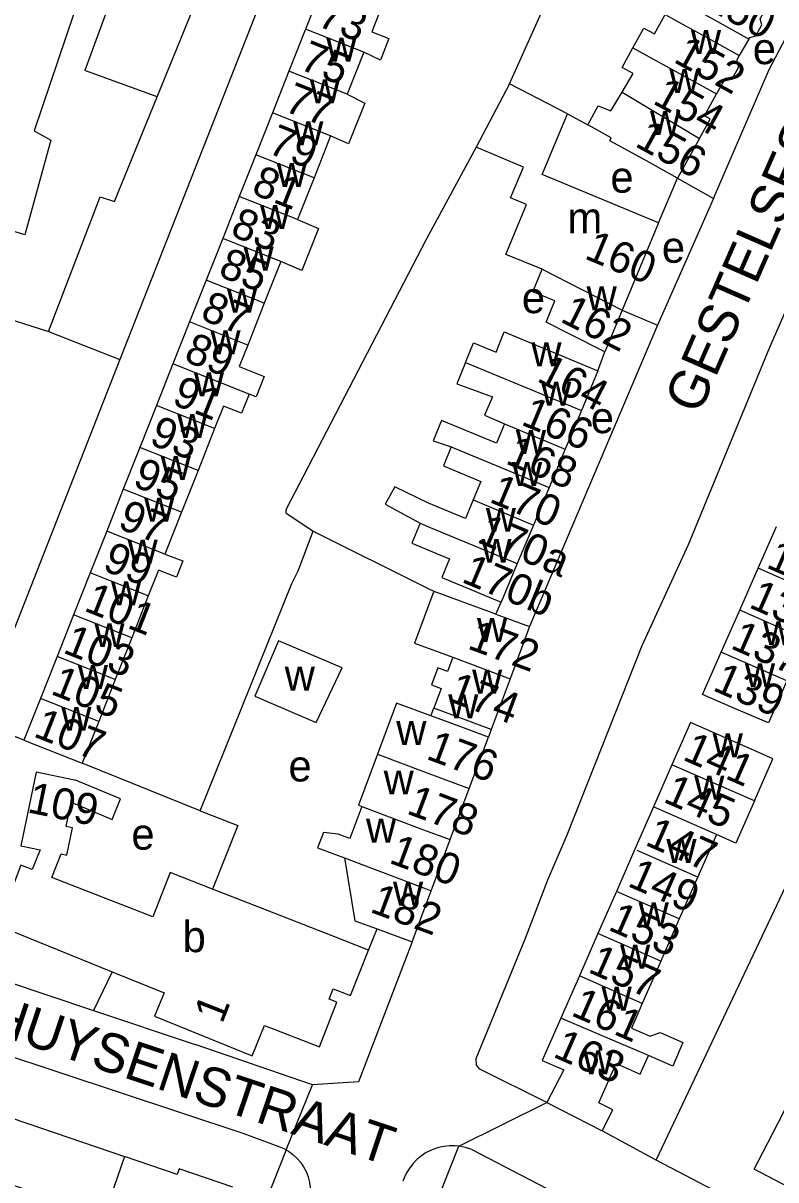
# Model space of a CAD drawing. Extents: x 159700 to 161346, y 381730 to 382922.
# Drawn here: x 160648.4 to 160744.8, y 381991.4 to 382139.7 of the extents above; entities that cross this region are included whole.
import ezdxf

# ---------------------------------------------------------------- set-up
doc = ezdxf.new("R2010")
doc.units = 0
for name, color, linetype in [('BLT_Basislijn', 7, 'Continuous'), ('BLT_Bebouwing', 7, 'Continuous'), ('BLT_Centroide', 7, 'Continuous'), ('BLT_Huisnummer', 7, 'Continuous'), ('BLT_Huisnummer_ tussenligend', 7, 'Continuous'), ('BLT_Huisnummer_reeks', 7, 'Continuous'), ('BLT_Onderdoorgang_en_onderverdeling', 7, 'Continuous'), ('BLT_Onderverdeling_panden', 7, 'Continuous'), ('BLT_Straatnaam', 7, 'Continuous'), ('BLT_Vlakafsluiter', 7, 'Continuous')]:
    doc.layers.add(name, color=color, linetype=linetype)

msp = doc.modelspace()

# ---------------------------------------------------------------- linework, layer by layer
at = {"layer": 'BLT_Basislijn'}
for p, q in [((160660.9, 382146.35), (160656.26, 382133.57)), ((160665.52, 382130.2), (160670.65, 382142.8)), ((160710.65, 382131.9), (160715.16, 382141.87)), ((160665.52, 382130.2), (160656.26, 382133.57)), ((160718.09, 382128.02), (160720.67, 382126.62)), ((160729.76, 382114.05), (160732.18, 382119.8)), ((160732.18, 382119.8), (160736.77, 382117.18)), ((160736.77, 382117.18), (160729.6, 382100.96)), ((160642.5, 382103.07), (160651.59, 382100.14)), ((160725.09, 382102.86), (160729.6, 382100.96)), ((160729.6, 382100.96), (160713.22, 382062.32)), ((160651.59, 382100.14), (160660.75, 382096.55)), ((160660.75, 382096.55), (160642.54, 382050.16)), ((160721.96, 382095.09), (160722.86, 382097.54)), ((160685.49, 382074.56), (160700, 382067.35)), ((160708.91, 382063.93), (160709.59, 382065.44)), ((160648.45, 382047.77), (160642.54, 382050.16)), ((160671.01, 382038.73), (160655.91, 382044.82)), ((160692.58, 382020.87), (160693.71, 382023.58)), ((160659.74, 382018.09), (160657.35, 382013.14)), ((160657.35, 382013.14), (160670.38, 382008.78)), ((160636.62, 382010.62), (160676.49, 381997.4)), ((160632.68, 382004.19), (160661.34, 381994.43)), ((160676.49, 381997.4), (160681.1, 381995.72)), ((160700, 381985.25), (160704.17, 381995.74)), ((160682.03, 381995.28), (160679.52, 381988.9)), ((160705.83, 381995.32), (160854.54, 381918.26))]:
    msp.add_line(p, q, dxfattribs=at)
for points in [[(160681.91, 382220.18), (160679.43, 382214.59), (160683.36, 382212.77), (160677.31, 382195.82), (160674.59, 382196.42), (160665.51, 382171.9), (160668.53, 382170.99), (160661.57, 382151.91), (160658.85, 382152.82), (160649.77, 382125.87), (160651.89, 382124.66), (160648.56, 382112.55), (160645.53, 382113.46), (160642.5, 382103.07)], [(160736.77, 382117.18), (160743.9, 382133.7), (160755.59, 382155.95), (160755.73, 382156.22)], [(160683.48, 382154.46), (160683.02, 382153.28), (160660.75, 382096.55)], [(160715.43, 382001.34), (160706.86, 382005.62), (160706.44, 382006.13), (160706.37, 382006.99), (160712.72, 382022.39), (160715.55, 382029.86), (160718.04, 382035.66), (160727.65, 382059.9), (160733.57, 382072.85), (160744.01, 382098.14), (160747.46, 382106.03), (160752.09, 382115.65), (160758.89, 382130.51), (160762.59, 382138.01), (160762.83, 382138.43)], [(160651.59, 382100.14), (160658.24, 382117.4), (160660.06, 382116.79), (160665.52, 382130.2)], [(160706.39, 382123.75), (160700, 382111.92)], [(160729.44, 381993.93), (160779.67, 382100.1), (160781.16, 382102.9), (160789.01, 382119.93)], [(160700, 382111.92), (160682, 382077.28), (160682, 382076.92), (160685.49, 382074.56)], [(160815.18, 382106.64), (160803.51, 382084.65), (160803.12, 382084.2), (160792.72, 382064.24), (160788.1, 382054.81), (160779.42, 382038.85), (160769.7, 382019.74), (160767.41, 382015.7), (160755.12, 381991.74), (160751.34, 381984.02), (160750.55, 381983.57), (160749.53, 381983.44), (160729.44, 381993.93)], [(160671.01, 382038.73), (160682.77, 382067.84), (160683.6, 382069.48), (160685.49, 382074.56)], [(160700, 382067.35), (160700.34, 382067.18), (160700.97, 382066.88)], [(160642.54, 382050.16), (160642.45, 382049.95), (160632.17, 382023.66), (160633.53, 382021.46), (160634.31, 382020.85), (160657.35, 382013.14)], [(160671.01, 382038.73), (160675.84, 382036.83), (160672.62, 382028.67)], [(160698.19, 382021.91), (160691.33, 382003.98), (160685.44, 382003.61)], [(160685.44, 382003.61), (160670.38, 382008.78)], [(160729.44, 381993.93), (160722.53, 381997.71)], [(160681.1, 381995.72), (160681.74, 381995.45), (160682.03, 381995.28)], [(160704.17, 381995.74), (160703.71, 381995.8), (160702.98, 381995.8), (160702.25, 381995.72), (160701.54, 381995.56), (160700.85, 381995.33), (160700.19, 381995.02), (160700, 381994.92)], [(160705.83, 381995.32), (160705.14, 381995.55), (160704.43, 381995.71), (160704.17, 381995.74)], [(160682.03, 381995.28), (160682.35, 381995.1), (160682.92, 381994.69), (160683.43, 381994.21), (160683.89, 381993.68), (160684.28, 381993.1), (160684.6, 381992.48), (160684.86, 381991.83), (160685.03, 381991.15), (160685.13, 381990.45), (160685.15, 381989.75), (160685.08, 381989.06), (160684.94, 381988.37), (160684.72, 381987.71), (160684.46, 381987.12)], [(160700, 381994.92), (160699.39, 381994.52), (160698.83, 381994.06), (160698.32, 381993.53), (160697.87, 381992.96), (160697.48, 381992.34), (160697.17, 381991.68), (160697.01, 381991.27)]]:
    msp.add_lwpolyline(points, dxfattribs=at)
at = {"layer": 'BLT_Bebouwing'}
for p, q in [((160686.65, 382144.24), (160684.53, 382138.88)), ((160684.53, 382138.88), (160682.4, 382133.52)), ((160741.32, 382137.61), (160740.08, 382135.53)), ((160691.98, 382135.93), (160689.86, 382130.57)), ((160682.4, 382133.52), (160680.28, 382128.16)), ((160710.65, 382131.9), (160706.39, 382123.75)), ((160718.09, 382128.02), (160710.65, 382131.9)), ((160680.28, 382128.16), (160678.16, 382122.8)), ((160714.86, 382120.27), (160718.09, 382128.02)), ((160687.74, 382125.21), (160685.62, 382119.85)), ((160734.98, 382124.88), (160732.18, 382119.8)), ((160678.16, 382122.8), (160676.04, 382117.44)), ((160729.76, 382114.05), (160714.86, 382120.27)), ((160685.62, 382119.85), (160683.49, 382114.49)), ((160676.04, 382117.44), (160673.92, 382112.08)), ((160729.76, 382114.05), (160725.09, 382102.86)), ((160673.92, 382112.08), (160671.8, 382106.72)), ((160681.37, 382109.13), (160679.25, 382103.77)), ((160671.8, 382106.72), (160669.67, 382101.36)), ((160679.25, 382103.77), (160677.13, 382098.41)), ((160725.09, 382102.86), (160722.86, 382097.54)), ((160669.67, 382101.36), (160667.55, 382096.01)), ((160667.55, 382096.01), (160665.43, 382090.65)), ((160721.96, 382095.09), (160719.86, 382090.03)), ((160665.43, 382090.65), (160663.31, 382085.29)), ((160719.86, 382090.03), (160717.79, 382085.08)), ((160672.88, 382087.7), (160670.76, 382082.34)), ((160663.31, 382085.29), (160661.18, 382079.93)), ((160717.79, 382085.08), (160715.73, 382080.14)), ((160670.76, 382082.34), (160668.64, 382076.98)), ((160715.73, 382080.14), (160713.72, 382075.33)), ((160661.18, 382079.93), (160659.06, 382074.57)), ((160668.64, 382076.98), (160666.52, 382071.62)), ((160659.06, 382074.57), (160656.94, 382069.21)), ((160713.72, 382075.33), (160711.65, 382070.39)), ((160742.51, 382069.8), (160744.86, 382075.17)), ((160711.65, 382070.39), (160709.59, 382065.44)), ((160740.15, 382064.42), (160742.51, 382069.8)), ((160656.94, 382069.21), (160654.82, 382063.85)), ((160664.39, 382066.26), (160662.27, 382060.9)), ((160654.82, 382063.85), (160652.7, 382058.49)), ((160708.91, 382063.93), (160713.22, 382062.32)), ((160737.79, 382059.05), (160740.15, 382064.42)), ((160713.22, 382062.32), (160710.74, 382055.65)), ((160662.27, 382060.9), (160660.15, 382055.54)), ((160652.7, 382058.49), (160650.58, 382053.13)), ((160660.15, 382055.54), (160658.03, 382050.18)), ((160710.74, 382055.65), (160708.32, 382049.14)), ((160650.58, 382053.13), (160648.45, 382047.77)), ((160700.6, 382050.89), (160700.96, 382051.87)), ((160658.03, 382050.18), (160655.91, 382044.82)), ((160708.32, 382049.14), (160707.95, 382048.15)), ((160705.51, 382041.59), (160707.95, 382048.15)), ((160731.47, 382044.62), (160729.1, 382039.21)), ((160703.07, 382035.03), (160705.51, 382041.59)), ((160729.1, 382039.21), (160726.72, 382033.8)), ((160737.16, 382035.68), (160734.78, 382030.27)), ((160700.63, 382028.47), (160703.07, 382035.03)), ((160689.52, 382032.68), (160690.84, 382024.64)), ((160726.72, 382033.8), (160724.35, 382028.39)), ((160734.78, 382030.27), (160732.41, 382024.86)), ((160678.77, 382026.27), (160672.62, 382028.67)), ((160700, 382026.77), (160700.63, 382028.47)), ((160724.35, 382028.39), (160721.98, 382022.98)), ((160698.19, 382021.91), (160700, 382026.77)), ((160645.11, 382024.03), (160659.74, 382018.09)), ((160690.84, 382024.64), (160693.71, 382023.58)), ((160732.41, 382024.86), (160730.04, 382019.44)), ((160693.71, 382023.58), (160698.19, 382021.91)), ((160721.98, 382022.98), (160719.61, 382017.57)), ((160730.04, 382019.44), (160727.66, 382014.03)), ((160719.61, 382017.57), (160717.23, 382012.16))]:
    msp.add_line(p, q, dxfattribs=at)
for points in [[(160741.32, 382137.61), (160741.44, 382137.82), (160742.2, 382138.04), (160742.98, 382139.46), (160742.75, 382140.23), (160744.13, 382142.74)], [(160694.1, 382141.28), (160693.02, 382138.55), (160695.21, 382137.68), (160694.12, 382134.93), (160691.98, 382135.93)], [(160726.47, 382136.51), (160727.86, 382139.03), (160729.21, 382138.28), (160730.58, 382140.77), (160732.45, 382139.74)], [(160725.08, 382130.81), (160726.51, 382133.2), (160725.08, 382133.99), (160726.47, 382136.51)], [(160740.08, 382135.53), (160739.73, 382134.89), (160739.99, 382134.01), (160739.2, 382132.58), (160738.28, 382132.56), (160737.19, 382130.59)], [(160689.86, 382130.57), (160692.11, 382129.42), (160690.04, 382124.18), (160687.74, 382125.21)], [(160720.67, 382126.62), (160722.01, 382129.05), (160723.65, 382128.42), (160725.08, 382130.81)], [(160734.98, 382124.88), (160736.34, 382127.36), (160735.63, 382127.76), (160737.19, 382130.59)], [(160732.18, 382119.8), (160727.8, 382122.21), (160723.51, 382124.58), (160723.7, 382124.95), (160720.67, 382126.62)], [(160714.86, 382108.12), (160710.18, 382110.02), (160712.85, 382116.42), (160710.8, 382117.28), (160712.44, 382121.22), (160706.39, 382123.75)], [(160683.49, 382114.49), (160686.19, 382113.34), (160684.06, 382107.96), (160681.37, 382109.13)], [(160722.86, 382097.54), (160718.4, 382099.79), (160715.37, 382101.33), (160716.48, 382104.05), (160713.65, 382105.23), (160714.86, 382108.12)], [(160705.02, 382096.18), (160706.05, 382098.68), (160708.93, 382097.5), (160709.99, 382100.08), (160721.96, 382095.09)], [(160677.13, 382098.41), (160676.03, 382095.65), (160679.25, 382094.37), (160678.22, 382091.76), (160677.31, 382092.12)], [(160705.02, 382096.18), (160703.9, 382093.45), (160704.96, 382093.06), (160708.46, 382091.78), (160707.46, 382089.4), (160710.02, 382088.32)], [(160677.31, 382092.12), (160676.34, 382089.67), (160674.03, 382090.59), (160672.88, 382087.7)], [(160710.02, 382088.32), (160708.97, 382085.81), (160701.96, 382088.74), (160700.88, 382086.15), (160703.2, 382085.37)], [(160703.2, 382085.37), (160702.19, 382082.94), (160707, 382080.93), (160706.01, 382078.55)], [(160695.95, 382080.24), (160694.74, 382078.03), (160699.2, 382075.59)], [(160706.01, 382078.55), (160705.01, 382076.17), (160700.27, 382078.15), (160695.95, 382080.24)], [(160699.2, 382075.59), (160698.13, 382073.03), (160700, 382072.25)], [(160666.52, 382071.62), (160668.81, 382070.76), (160667.98, 382068.67), (160665.71, 382069.57), (160664.39, 382066.26)], [(160700, 382072.25), (160702.96, 382071.01), (160701.97, 382068.63), (160704.98, 382067.37), (160709.59, 382065.44)], [(160700.97, 382066.88), (160698.48, 382060.21), (160703.39, 382058.39)], [(160700.97, 382066.88), (160708.54, 382064.07), (160708.91, 382063.93)], [(160703.39, 382058.39), (160702.72, 382056.57), (160701.48, 382057.03), (160700.67, 382054.85), (160701.9, 382054.39), (160700.96, 382051.87)], [(160746.19, 382055.37), (160743.83, 382049.99), (160739.98, 382051.6), (160735.4, 382053.61), (160737.79, 382059.05)], [(160700.6, 382050.89), (160696.2, 382052.52), (160693.76, 382045.96)], [(160742.03, 382039.99), (160744.4, 382045.4), (160741.9, 382046.49), (160738.42, 382048.02), (160733.84, 382050.03), (160731.47, 382044.62)], [(160648.45, 382047.77), (160653.1, 382045.93), (160655.91, 382044.82)], [(160693.76, 382045.96), (160691.33, 382039.44), (160691.73, 382039.29)], [(160672.62, 382028.67), (160667.2, 382030.8), (160664.98, 382025.12), (160652.03, 382030.19), (160653.21, 382033.2), (160653.95, 382033.05), (160654.67, 382036.53), (160653.85, 382036.7), (160654.49, 382039.81), (160659.76, 382037.62), (160660.84, 382040.24), (160655.08, 382042.63), (160654.92, 382042.66), (160650.02, 382043.67), (160648.07, 382034.22), (160650.52, 382033.71), (160649.53, 382031.19), (160648.07, 382031.76), (160645.11, 382024.03)], [(160742.03, 382039.99), (160739.67, 382034.59), (160737.16, 382035.68)], [(160691.73, 382039.29), (160690.19, 382035.17), (160688.69, 382035.73), (160686.81, 382035.93), (160686.08, 382033.96), (160689.52, 382032.68)], [(160692.58, 382020.87), (160687.92, 382022.69), (160678.77, 382026.27)], [(160659.74, 382018.09), (160666.41, 382015.39), (160665.2, 382012.39), (160677.7, 382007.32), (160679.28, 382011.2), (160686.32, 382008.47), (160688.55, 382014.21), (160687.55, 382014.6), (160688.06, 382015.9), (160690.29, 382015.03), (160692.58, 382020.87)], [(160727.66, 382014.03), (160726.28, 382010.88), (160728.66, 382009.84), (160729.94, 382010.32), (160732.88, 382009.04), (160731.56, 382006.01), (160728.45, 382007.36)], [(160717.23, 382012.16), (160714.86, 382006.74), (160717.6, 382005.54), (160715.43, 382001.34)], [(160722.53, 381997.71), (160723.9, 382000.39), (160722.09, 382001.31), (160724.3, 382006.35), (160727.41, 382004.99), (160728.45, 382007.36)], [(160715.43, 382001.34), (160722.53, 381997.71)], [(160753.56, 381996.34), (160749.64, 381988.8), (160741.98, 381992.78), (160744.29, 381997.22), (160745.9, 382000.32)], [(160661.34, 381994.43), (160658.67, 381986.71), (160646.51, 381990.91), (160646.97, 381992.25), (160641.84, 381994.02), (160641.37, 381992.68), (160630.13, 381996.56)], [(160675.22, 381990.48), (160668.35, 381992.85), (160668.09, 381992.1), (160661.34, 381994.43)]]:
    msp.add_lwpolyline(points, dxfattribs=at)
msp.add_lwpolyline([(160681.08, 382060.51), (160678.05, 382053.41), (160685.91, 382050.05), (160689.21, 382057.04)], close=True, dxfattribs=at)
at = {"layer": 'BLT_Onderdoorgang_en_onderverdeling'}
for points in [[(160741.32, 382137.61), (160736.94, 382140.03), (160733.62, 382141.86)], [(160732.45, 382139.74), (160735.7, 382137.94), (160740.08, 382135.53)], [(160708.32, 382049.14), (160703.63, 382050.88), (160700.96, 382051.87)], [(160707.95, 382048.15), (160703.27, 382049.9), (160700.6, 382050.89)]]:
    msp.add_lwpolyline(points, dxfattribs=at)
at = {"layer": 'BLT_Onderverdeling_panden'}
for p, q in [((160691.98, 382135.93), (160684.53, 382138.88)), ((160726.47, 382136.51), (160737.19, 382130.59)), ((160689.86, 382130.57), (160682.4, 382133.52)), ((160725.08, 382130.81), (160734.98, 382124.88)), ((160687.74, 382125.21), (160680.28, 382128.16)), ((160685.62, 382119.85), (160678.16, 382122.8)), ((160683.49, 382114.49), (160676.04, 382117.44)), ((160681.37, 382109.13), (160673.92, 382112.08)), ((160679.25, 382103.77), (160671.8, 382106.72)), ((160714.86, 382108.12), (160725.09, 382102.86)), ((160677.13, 382098.41), (160669.67, 382101.36)), ((160677.31, 382092.12), (160667.55, 382096.01)), ((160705.02, 382096.18), (160719.86, 382090.03)), ((160672.88, 382087.7), (160665.43, 382090.65)), ((160710.02, 382088.32), (160717.79, 382085.08)), ((160670.76, 382082.34), (160663.31, 382085.29)), ((160703.2, 382085.37), (160715.73, 382080.14)), ((160668.64, 382076.98), (160661.18, 382079.93)), ((160706.01, 382078.55), (160713.72, 382075.33)), ((160699.2, 382075.59), (160700, 382075.25)), ((160666.52, 382071.62), (160659.06, 382074.57)), ((160700, 382075.25), (160711.65, 382070.39)), ((160750.9, 382066.12), (160742.51, 382069.8)), ((160664.39, 382066.26), (160656.94, 382069.21)), ((160662.27, 382060.9), (160654.82, 382063.85)), ((160748.55, 382060.74), (160740.15, 382064.42)), ((160660.15, 382055.54), (160652.7, 382058.49)), ((160703.39, 382058.39), (160710.74, 382055.65)), ((160746.19, 382055.37), (160737.79, 382059.05)), ((160658.03, 382050.18), (160650.58, 382053.13)), ((160693.76, 382045.96), (160700, 382043.64)), ((160742.03, 382039.99), (160731.47, 382044.62)), ((160700, 382043.64), (160705.51, 382041.59)), ((160691.73, 382039.29), (160700, 382036.17)), ((160737.16, 382035.68), (160729.1, 382039.21)), ((160700, 382036.17), (160703.07, 382035.03)), ((160689.52, 382032.68), (160700, 382028.7)), ((160734.76, 382030.23), (160727.01, 382033.63)), ((160700, 382028.7), (160700.63, 382028.47)), ((160732.41, 382024.86), (160724.35, 382028.39)), ((160730.04, 382019.44), (160721.98, 382022.98)), ((160727.66, 382014.03), (160719.61, 382017.57)), ((160728.45, 382007.36), (160717.23, 382012.16))]:
    msp.add_line(p, q, dxfattribs=at)
at = {"layer": 'BLT_Vlakafsluiter'}
for p, q in [((160682.03, 381995.28), (160685.44, 382003.61)), ((160704.17, 381995.74), (160715.43, 382001.34))]:
    msp.add_line(p, q, dxfattribs=at)

# ---------------------------------------------------------------- texts
at = {"layer": 'BLT_Centroide'}
for s, p in [('w', (160733.89, 382135.69)), ('w', (160687.19, 382134.72)), ('e', (160741.82, 382134.4)), ('w', (160731.14, 382130.69)), ('w', (160685.07, 382129.38)), ('w', (160728.66, 382125.31)), ('w', (160682.95, 382124)), ('w', (160680.83, 382118.66)), ('e', (160723.58, 382117.93)), ('w', (160678.7, 382113.28)), ('m', (160718.08, 382112.7)), ('e', (160730.17, 382108.95)), ('w', (160676.58, 382107.94)), ('w', (160674.46, 382102.56)), ('e', (160712.24, 382102.49)), ('w', (160720.53, 382102.84)), ('w', (160672.34, 382097.22)), ('w', (160713.45, 382095.66)), ('w', (160670.22, 382091.84)), ('w', (160714.7, 382090.62)), ('w', (160668.09, 382086.5)), ('e', (160721.07, 382087.11)), ('w', (160711.47, 382084.44)), ('w', (160665.97, 382081.12)), ('w', (160710.98, 382080.34)), ('w', (160663.85, 382075.78)), ('w', (160707.62, 382074.47)), ('w', (160661.73, 382070.41)), ('w', (160707.05, 382070.5)), ('w', (160659.61, 382065.06)), ('w', (160657.48, 382059.69)), ('w', (160706.49, 382060.34)), ('w', (160743.16, 382059.91)), ('w', (160655.36, 382054.34)), ('w', (160681.86, 382054.11)), ('w', (160705.86, 382053.75)), ('w', (160740.81, 382054.53)), ('w', (160702.8, 382050.58)), ('w', (160653.24, 382048.97)), ('w', (160696.15, 382047.14)), ('w', (160736.68, 382045.56)), ('e', (160682.34, 382042.48)), ('w', (160694.53, 382040.81)), ('w', (160734.32, 382040.16)), ('w', (160692.27, 382034.65)), ('e', (160662.22, 382033.74)), ('w', (160730.75, 382032.05)), ('w', (160695.73, 382026.56)), ('w', (160727.2, 382023.91)), ('b', (160668.78, 382020.61)), ('w', (160724.82, 382018.5)), ('w', (160722.45, 382013.09)), ('w', (160720.08, 382004.94))]:
    msp.add_text(s, height=4, dxfattribs=at).set_placement(p)
at = {"layer": 'BLT_Huisnummer'}
for s, rotation, p in [('73', 338.399, (160685.85, 382139.37)), ('152', 331.1371, (160731.52, 382134.74)), ('77', 338.399, (160681.62, 382128.47)), ('156', 331.1272, (160726.57, 382123.96)), ('81', 338.399, (160677.45, 382117.85)), ('160', 337.3404, (160720.11, 382109.55)), ('85', 338.399, (160673.19, 382107.3)), ('162', 333.1186, (160717.01, 382101.47)), ('89', 338.399, (160668.79, 382096.42)), ('164', 333.1186, (160714, 382093.84)), ('93', 338.399, (160664.36, 382085.76)), ('170', 337.3439, (160707.92, 382078.34)), ('97', 338.399, (160660.32, 382074.99)), ('170a', 337.3431, (160706.33, 382073.2)), ('129', 336.3109, (160743.4, 382069.95)), ('170b', 337.3431, (160704.36, 382068.09)), ('101', 338.399, (160656.01, 382064.4)), ('133', 336.3109, (160741.17, 382064.84)), ('172', 339.5962, (160705.13, 382059.56)), ('105', 338.399, (160651.73, 382053.74)), ('139', 336.3214, (160736.53, 382054.22)), ('107', 338.3965, (160649.53, 382048.29)), ('176', 339.596, (160699.84, 382045.41)), ('141', 336.3192, (160732.68, 382045.32)), ('145', 336.3109, (160730.2, 382039.92)), ('149', 336.3109, (160725.63, 382029.13)), ('182', 339.6003, (160692.63, 382025.8)), ('153', 336.3109, (160723.14, 382023.52)), ('157', 336.3109, (160720.57, 382018.1)), ('161', 336.3109, (160718.39, 382012.56)), ('1', 68.6358, (160673.85, 382011.32)), ('163', 336.3109, (160716.08, 382007.24))]:
    msp.add_text(s, height=4, rotation=rotation, dxfattribs=at).set_placement(p)
at = {"layer": 'BLT_Huisnummer_ tussenligend'}
for s, rotation, p in [('150', 331.1403, (160735.45, 382141.75)), ('75', 338.399, (160683.57, 382133.83)), ('154', 331.1371, (160728.85, 382129.43)), ('79', 338.399, (160679.51, 382123.09)), ('83', 338.399, (160674.75, 382112.48)), ('87', 338.399, (160670.9, 382101.76)), ('91', 338.399, (160667.26, 382090.87)), ('166', 337.3419, (160711.99, 382088.25)), ('168', 337.3419, (160710, 382083.27)), ('95', 338.399, (160662.24, 382080.38)), ('99', 338.399, (160658.37, 382069.61)), ('103', 338.399, (160653.31, 382059.02)), ('137', 336.3192, (160738.81, 382059.59)), ('174', 339.5962, (160702.59, 382052.86)), ('178', 339.596, (160697.32, 382038.41)), ('147', 336.3109, (160727.87, 382034.4)), ('180', 339.5935, (160695.07, 382032.1))]:
    msp.add_text(s, height=4, rotation=rotation, dxfattribs=at).set_placement(p)
at = {"layer": 'BLT_Huisnummer_reeks'}
msp.add_text('109', height=4, rotation=348.3238, dxfattribs=at).set_placement((160648.76, 382038.55))
at = {"layer": 'BLT_Straatnaam'}
for s, rotation, p in [('GESTELSESTRAAT', 66.3471, (160734.94, 382089.34)), ('CAMPHUYSENSTRAAT', 341.4268, (160625.12, 382016.68))]:
    msp.add_text(s, height=5, rotation=rotation, dxfattribs=at).set_placement(p)

doc.saveas('drawing.dxf')
